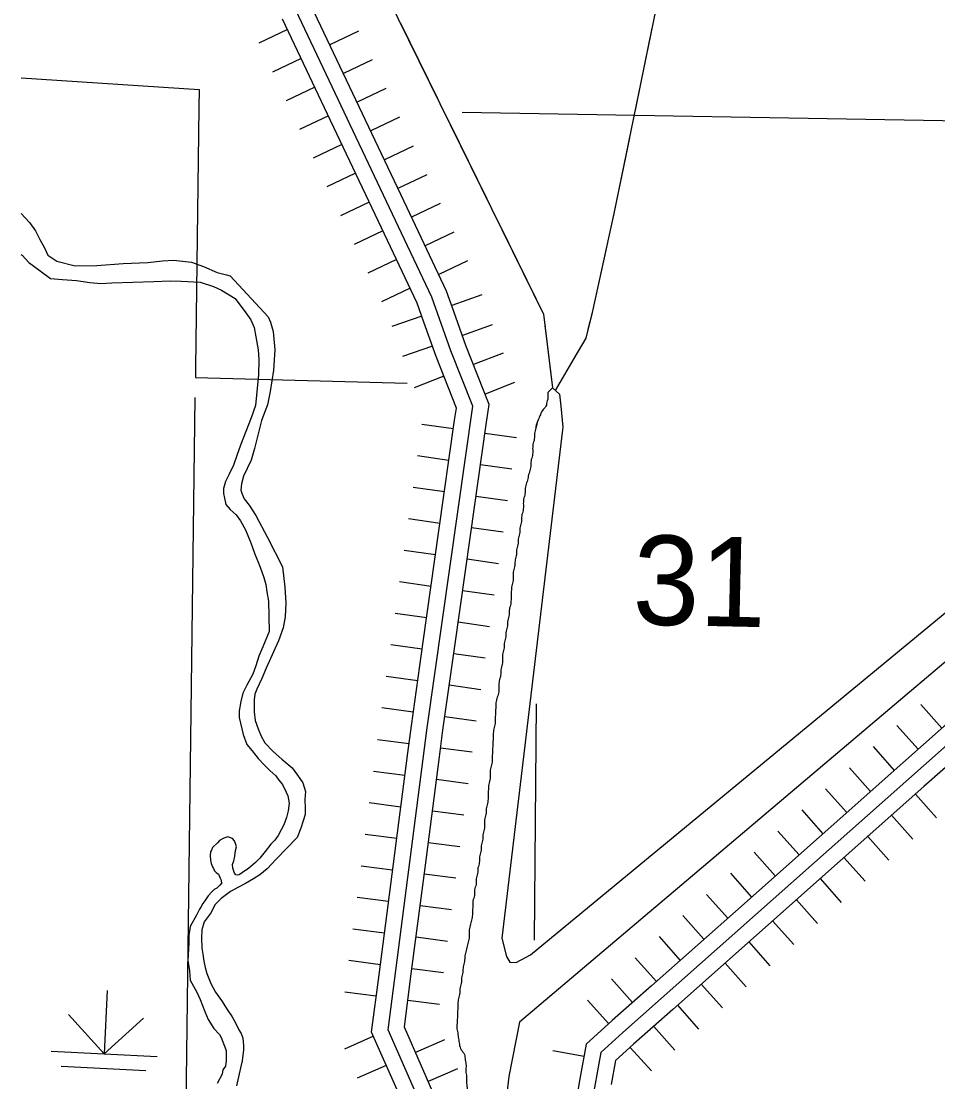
# Model space of a CAD drawing. Extents: x -4306 to 3843, y 131 to 8341.
# Drawn here: x -2796 to -2104, y 5516 to 6317 of the extents above; entities that cross this region are included whole.
import ezdxf

# ---------------------------------------------------------------- set-up
doc = ezdxf.new("R2010")
doc.units = 0
for name, color, linetype in [('32', 7, 'Continuous'), ('4', 7, 'Continuous'), ('52', 7, 'Continuous'), ('54', 7, 'Continuous'), ('55', 7, 'Continuous'), ('56', 7, 'Continuous'), ('59', 7, 'Continuous'), ('63', 7, 'Continuous')]:
    doc.layers.add(name, color=color, linetype=linetype)

msp = doc.modelspace()

# ---------------------------------------------------------------- linework, layer by layer
at = {"layer": '32'}
for p, q in [((-2486.06, 6108.61), (-2632.58, 6417.58)), ((-2486.06, 6108.61), (-2632.58, 6417.58)), ((-2540.91, 6252.29), (-2577.11, 6328.63)), ((-2562.6, 6242.01), (-2598.8, 6318.35)), ((-2504.71, 6175.95), (-2540.91, 6252.29)), ((-2526.4, 6165.67), (-2562.6, 6242.01)), ((-2474.95, 6113.2), (-2504.71, 6175.95)), ((-2497.17, 6104.03), (-2526.4, 6165.67)), ((-2471.68, 6068.01), (-2486.06, 6108.61)), ((-2471.68, 6068.01), (-2486.06, 6108.61)), ((-2469.52, 6097.86), (-2474.95, 6113.2)), ((-2492.15, 6089.85), (-2497.17, 6104.03)), ((-2460.43, 6072.21), (-2469.52, 6097.86)), ((-2482.93, 6063.81), (-2492.15, 6089.85)), ((-2455.31, 6026.29), (-2471.68, 6068.01)), ((-2455.31, 6026.29), (-2471.68, 6068.01)), ((-2442.98, 6027.73), (-2460.43, 6072.21)), ((-2467.63, 6024.84), (-2482.93, 6063.81)), ((-2489.69, 5783.46), (-2455.31, 6026.29)), ((-2489.69, 5783.46), (-2455.31, 6026.29)), ((-2468.91, 6015.84), (-2467.63, 6024.84)), ((-2445.14, 6012.48), (-2442.98, 6027.73)), ((-2480.75, 5932.19), (-2468.91, 6015.84)), ((-2456.98, 5928.82), (-2445.14, 6012.48)), ((-2492.59, 5848.53), (-2480.75, 5932.19)), ((-2468.83, 5845.17), (-2456.98, 5928.82)), ((-2501.58, 5785.07), (-2492.59, 5848.53)), ((-2477.79, 5781.84), (-2468.83, 5845.17)), ((-2011.81, 5846.53), (-2341.92, 5553.64)), ((-2011.81, 5846.53), (-2341.92, 5553.64)), ((-2067.43, 5813.23), (-2130.63, 5757.16)), ((-2051.5, 5795.27), (-2114.7, 5739.2)), ((-2519.23, 5555.73), (-2489.69, 5783.46)), ((-2519.23, 5555.73), (-2489.69, 5783.46)), ((-2504.22, 5764.71), (-2501.58, 5785.07)), ((-2480.42, 5761.62), (-2477.79, 5781.84)), ((-2515.09, 5680.92), (-2504.22, 5764.71)), ((-2491.29, 5677.83), (-2480.42, 5761.62)), ((-2130.63, 5757.16), (-2193.83, 5701.08)), ((-2114.7, 5739.2), (-2177.9, 5683.13)), ((-2193.83, 5701.08), (-2257.03, 5645.01)), ((-2525.96, 5597.13), (-2515.09, 5680.92)), ((-2502.16, 5594.05), (-2491.29, 5677.83)), ((-2177.9, 5683.13), (-2241.09, 5627.05)), ((-2257.03, 5645.01), (-2320.22, 5588.93)), ((-2241.09, 5627.05), (-2304.29, 5570.98)), ((-2531.57, 5553.96), (-2525.96, 5597.13)), ((-2506.9, 5557.51), (-2502.16, 5594.05)), ((-2320.22, 5588.93), (-2349.93, 5562.57)), ((-2304.29, 5570.98), (-2333.91, 5544.71)), ((-2493.45, 5497.18), (-2519.23, 5555.73)), ((-2493.45, 5497.18), (-2519.23, 5555.73)), ((-2490.4, 5520.03), (-2506.9, 5557.51)), ((-2349.93, 5562.57), (-2369.59, 5544.75)), ((-2512.37, 5510.35), (-2531.57, 5553.96)), ((-2341.92, 5553.64), (-2358.5, 5538.6)), ((-2341.92, 5553.64), (-2358.5, 5538.6)), ((-2369.59, 5544.75), (-2374.3, 5518.64)), ((-2333.91, 5544.71), (-2347.42, 5532.45)), ((-2358.5, 5538.6), (-2381.79, 5409.56)), ((-2358.5, 5538.6), (-2381.79, 5409.56)), ((-2347.42, 5532.45), (-2350.68, 5514.38)), ((-2481.02, 5498.73), (-2490.4, 5520.03)), ((-2374.3, 5518.64), (-2389.31, 5435.49))]:
    msp.add_line(p, q, dxfattribs=at)
at = {"layer": '4'}
msp.add_line((-2672.44, 5429.89), (-2664.73, 6032.85), dxfattribs=at)
at = {"layer": '52'}
msp.add_line((-2012.57, 6240.1), (-2463.12, 6248.01), dxfattribs=at)
at = {"layer": '54'}
for p, q in [((-2796.1, 6274.18), (-2661.76, 6265.26)), ((-2661.76, 6265.26), (-2661.94, 6251.5)), ((-2661.94, 6251.5), (-2664.44, 6055.47)), ((-2664.44, 6055.47), (-2664.54, 6047.98)), ((-2664.54, 6047.98), (-2504.64, 6043.66)), ((-2407.42, 5801.55), (-2408.93, 5623.21))]:
    msp.add_line(p, q, dxfattribs=at)
at = {"layer": '55'}
for p, q in [((-2796.1, 6171.68), (-2789.78, 6164.88)), ((-2789.78, 6164.88), (-2785.37, 6158.73)), ((-2785.37, 6158.73), (-2781.93, 6152.26)), ((-2781.93, 6152.26), (-2778.48, 6145.8)), ((-2778.48, 6145.8), (-2775.99, 6140.31)), ((-2775.99, 6140.31), (-2769.32, 6135.73)), ((-2769.32, 6135.73), (-2755.29, 6132.34)), ((-2755.29, 6132.34), (-2738.98, 6132.46)), ((-2738.98, 6132.46), (-2719.13, 6134.13)), ((-2719.13, 6134.13), (-2700.57, 6134.87)), ((-2700.57, 6134.87), (-2689.37, 6136.01)), ((-2689.37, 6136.01), (-2681.04, 6136.55)), ((-2681.04, 6136.55), (-2667.63, 6135.1)), ((-2667.63, 6135.1), (-2658.39, 6131.77)), ((-2658.39, 6131.77), (-2648.21, 6127.15)), ((-2648.21, 6127.15), (-2641.19, 6125.45)), ((-2641.19, 6125.45), (-2638.36, 6124.65))]:
    msp.add_line(p, q, dxfattribs=at)
for points in [[(-2796.1, 6140.83), (-2795.5, 6140.23), (-2790.44, 6134.71), (-2781.88, 6128.5), (-2773.95, 6122.62), (-2765, 6121.86), (-2754.46, 6121.09), (-2744.24, 6119.68), (-2735.93, 6118.93), (-2727.61, 6119.47), (-2695.94, 6120.36), (-2683.78, 6120.85), (-2675.47, 6120.74), (-2661.08, 6119.92), (-2650.89, 6116.58), (-2644.84, 6113.94), (-2634.68, 6107.71), (-2626.48, 6096.69), (-2622.71, 6091.5), (-2620.21, 6085.69), (-2619.01, 6078.61), (-2617.2, 6068.96), (-2616.65, 6061.24), (-2617.1, 6050.01), (-2618.55, 6034.61), (-2619.27, 6026.92), (-2622.58, 6017.64), (-2630.49, 5996.87), (-2633.45, 5989.2), (-2635.77, 5981.84), (-2639.05, 5975.14), (-2641.99, 5969.4), (-2643.33, 5964.28), (-2643.37, 5960.42), (-2642.77, 5956.89), (-2641.55, 5952.05), (-2638.39, 5948.48), (-2633.96, 5944.25), (-2630.49, 5939.71), (-2626.73, 5932.92), (-2622.68, 5923.24), (-2619.89, 5915.5), (-2615.85, 5904.85), (-2613.06, 5897.11), (-2611.52, 5891.63), (-2610.63, 5886.16), (-2609.43, 5879.08), (-2609.04, 5856.27), (-2613.65, 5844.77), (-2616.61, 5837.74), (-2618.93, 5830.39), (-2621.24, 5823.99), (-2625.81, 5815.7), (-2628.76, 5809.64), (-2630.43, 5803.56), (-2631.46, 5796.51), (-2631.52, 5791.37), (-2628.47, 5778.49), (-2625.67, 5771.07), (-2621.89, 5766.2), (-2617.16, 5760.36), (-2612.42, 5755.49), (-2608.31, 5751.26), (-2603.87, 5747.35), (-2601.67, 5744.11)], [(-2638.36, 6124.65), (-2609.62, 6093.7), (-2608.01, 6089.71), (-2605.86, 6082.62), (-2604.73, 6068.8), (-2605.54, 6053.4), (-2608.28, 6037.37), (-2610.31, 6027.45), (-2614.61, 6015.62), (-2619.96, 5994.49), (-2622.62, 5985.53), (-2628.19, 5973.4), (-2629.86, 5967.64), (-2630.23, 5962.83), (-2629.3, 5959.93), (-2627.74, 5956.38), (-2623.96, 5951.51), (-2618.93, 5943.74), (-2610.16, 5927.26), (-2598.9, 5904.96), (-2597.15, 5889.84), (-2596.33, 5877.95), (-2596.77, 5867.36), (-2598.46, 5859.03), (-2601.77, 5849.12), (-2605.7, 5840.82), (-2611.27, 5828.69), (-2614.56, 5820.7), (-2618.17, 5812.72), (-2619.81, 5808.88), (-2620.18, 5804.71), (-2620.28, 5795.72), (-2619.4, 5788.97), (-2617.23, 5782.84), (-2615.05, 5777.35), (-2612.23, 5772.18), (-2605.91, 5765.68), (-2599.26, 5759.82), (-2591.65, 5753.3), (-2587.56, 5747.79), (-2583.47, 5741.96), (-2581.62, 5735.51), (-2582.01, 5729.42), (-2581.76, 5722.99), (-2581.82, 5718.17), (-2583.15, 5713.37), (-2585.13, 5707.94), (-2587.77, 5700.91), (-2603.62, 5684.41), (-2610.42, 5677.11), (-2615.91, 5672.68), (-2620.74, 5669.53), (-2626.86, 5666.08), (-2632.01, 5663.25), (-2638.12, 5660.11), (-2645.21, 5654.74), (-2650.06, 5649.99), (-2652.69, 5644.24), (-2657.88, 5637.24), (-2659.87, 5631.17), (-2659.94, 5625.07), (-2659.71, 5617.36), (-2659.12, 5612.85), (-2658.22, 5607.38)], [(-2601.67, 5744.11), (-2598.83, 5740.87), (-2596.02, 5735.05), (-2594.77, 5732.14), (-2593.87, 5726.67), (-2594.58, 5720.9), (-2595.91, 5715.78), (-2597.89, 5710.35), (-2599.86, 5706.52), (-2602.14, 5702.37), (-2604.74, 5698.87), (-2607.65, 5695.7), (-2611.87, 5690.29), (-2616.09, 5685.21), (-2619.32, 5682.04), (-2622.87, 5678.87), (-2625.46, 5676.65), (-2628.03, 5675.08), (-2629, 5674.45), (-2631.58, 5672.56), (-2633.18, 5672.26), (-2634.14, 5672.59), (-2635.08, 5673.88), (-2635.7, 5675.5), (-2636.32, 5677.75), (-2636.61, 5680.33), (-2635.62, 5683.2), (-2634.94, 5686.73), (-2634.25, 5690.89), (-2633.58, 5693.78), (-2634.2, 5695.39), (-2635.13, 5698.29), (-2636.71, 5699.92), (-2640.21, 5701.24), (-2643.1, 5700.32), (-2646.32, 5698.43), (-2647.94, 5696.85), (-2651.81, 5693.36), (-2652.48, 5691.12), (-2653.13, 5689.85), (-2653.48, 5687.28), (-2653.2, 5683.75), (-2652.59, 5681.17), (-2651.66, 5678.59), (-2651.04, 5677.3), (-2650.09, 5675.68), (-2648.83, 5674.38), (-2647.25, 5673.07), (-2646.3, 5671.46), (-2646, 5670.17), (-2645.06, 5668.55), (-2645.07, 5667.59), (-2644.76, 5666.62), (-2646.06, 5664.71), (-2648.32, 5662.49), (-2650.57, 5661.56), (-2651.87, 5659.97), (-2655.1, 5656.8), (-2657.39, 5652.97), (-2659.01, 5651.06), (-2660.64, 5648.19), (-2661.62, 5646.6), (-2663.9, 5642.13), (-2668.48, 5633.52), (-2669.51, 5626.79), (-2669.57, 5621.65), (-2669.95, 5616.84), (-2670.37, 5607.86), (-2669.17, 5600.13), (-2668.61, 5593.06), (-2663.6, 5584.01), (-2661.1, 5578.52), (-2657.37, 5569.48), (-2654.88, 5563.35), (-2650.8, 5556.55), (-2646.37, 5552), (-2645.12, 5549.74), (-2642.63, 5543.28), (-2641.39, 5540.06), (-2641.44, 5535.56), (-2641.47, 5532.35), (-2641.84, 5528.18), (-2643.79, 5525.32), (-2644.47, 5522.11), (-2648.07, 5515.09)], [(-2658.22, 5607.38), (-2657.31, 5602.55), (-2656.09, 5598.04), (-2652.97, 5590.62), (-2649.53, 5584.15), (-2644.8, 5577.67), (-2640.72, 5570.88), (-2636.95, 5565.37), (-2634.44, 5560.84), (-2631.94, 5555.67), (-2630.05, 5552.76), (-2628.81, 5549.21), (-2628.23, 5543.75), (-2628.27, 5540.54), (-2629.32, 5532.2), (-2630.33, 5528.04), (-2631.67, 5522.28), (-2632.68, 5517.79), (-2633.69, 5513.31)]]:
    msp.add_lwpolyline(points, dxfattribs=at)
at = {"layer": '56'}
for points in [[(-2392.7, 6038.06), (-2378.61, 6062.32), (-2369.74, 6077.64), (-2364.92, 6097.03), (-2348.42, 6171.82), (-2328.07, 6270.89), (-2309.27, 6363.02), (-2286.24, 6472.38), (-2273.45, 6535.73), (-2258.92, 6600.19), (-2235.62, 6710.03), (-2217.15, 6800.47), (-2203.6, 6884.38), (-2197.49, 6944.9), (-2195.73, 7000.54), (-2194.77, 7093.35)], [(-2796.1, 6893.32), (-2660.35, 6614.55), (-2519.4, 6334.93), (-2401.78, 6095.82), (-2394.95, 6040.1)], [(-2509.83, 6315.47), (-2481.86, 6258.61)], [(-2332.44, 6249.65), (-2328.07, 6270.89), (-2319.74, 6311.73)], [(-2472.53, 6239.66), (-2444.56, 6182.8)], [(-2349.5, 6166.9), (-2348.42, 6171.82), (-2336.68, 6228.96)], [(-2435.24, 6163.85), (-2407.27, 6106.99)], [(-2368.04, 6084.48), (-2364.92, 6097.03), (-2354.05, 6146.28)], [(-2400.72, 6087.21), (-2394.95, 6040.1)], [(-2398.45, 6031.65), (-2398.26, 6036.99), (-2394.95, 6040.1), (-2389.74, 6035.36), (-2388.72, 6026.47), (-2387.16, 6010.6), (-2387.62, 6008.6), (-2433.19, 5624.79), (-2429.83, 5610.94), (-2427.32, 5606.74), (-2422.53, 5606.36), (-2411.59, 5612.32), (-2032.72, 5924.64)], [(-2017.93, 5901.63), (-2419.98, 5561.32)], [(-2419.98, 5561.32), (-2428.14, 5520.43), (-2455.18, 5291.97), (-2489.16, 5041.29), (-2521.81, 4920.48), (-2538.06, 4862.99), (-2570.96, 4832.09), (-2659.53, 4768.87)]]:
    msp.add_lwpolyline(points, dxfattribs=at)
for points in [[(-2398.45, 6031.65), (-2399.02, 6030.37), (-2400.06, 6026.24), (-2402.72, 6023.03), (-2404.59, 6018.94), (-2406.46, 6014.86), (-2407.5, 6010.73), (-2406.51, 6014.02), (-2407.54, 6009.9), (-2408.58, 6005.77), (-2408.78, 6001.6), (-2409.82, 5997.48), (-2410.02, 5993.31), (-2410.23, 5989.14), (-2411.27, 5985.01), (-2411.47, 5980.84), (-2412.51, 5976.72), (-2413.54, 5972.59), (-2414.58, 5968.46), (-2415.62, 5964.34), (-2415.82, 5960.17), (-2416.86, 5956.04), (-2417.06, 5951.87), (-2417.27, 5947.71), (-2418.3, 5943.58), (-2418.51, 5939.41), (-2419.55, 5935.28), (-2419.75, 5931.12), (-2420.79, 5926.99), (-2420.99, 5922.82), (-2422.03, 5918.69), (-2422.23, 5914.53), (-2423.27, 5910.4), (-2423.47, 5906.23), (-2424.51, 5902.1), (-2424.71, 5897.94), (-2424.92, 5893.77), (-2425.95, 5889.64), (-2426.16, 5885.47), (-2426.36, 5881.3), (-2426.57, 5877.14), (-2427.6, 5873.01), (-2427.81, 5868.84), (-2428.84, 5864.71), (-2429.05, 5860.55), (-2430.08, 5856.42), (-2430.29, 5852.25), (-2431.33, 5848.13), (-2431.53, 5843.96), (-2432.57, 5839.83), (-2432.77, 5835.66), (-2432.97, 5831.49), (-2434.01, 5827.37), (-2434.22, 5823.2), (-2435.25, 5819.07), (-2435.46, 5814.9), (-2435.66, 5810.74), (-2436.7, 5806.61), (-2437.73, 5802.48), (-2437.94, 5798.31), (-2438.14, 5794.15), (-2438.35, 5789.98), (-2438.55, 5785.81), (-2439.59, 5781.68), (-2439.79, 5777.52), (-2439.99, 5773.35), (-2440.2, 5769.18), (-2440.4, 5765.01), (-2440.61, 5760.84), (-2440.81, 5756.68), (-2441.85, 5752.55), (-2442.05, 5748.38), (-2442.25, 5744.21), (-2443.29, 5740.09), (-2443.5, 5735.92), (-2443.7, 5731.75), (-2443.9, 5727.58), (-2444.94, 5723.46), (-2445.14, 5719.29), (-2446.18, 5715.16), (-2446.39, 5710.99), (-2446.59, 5706.83), (-2447.63, 5702.7), (-2447.83, 5698.53), (-2448.87, 5694.4), (-2449.07, 5690.24), (-2450.11, 5686.11), (-2450.31, 5681.94), (-2451.35, 5677.81)], [(-2451.35, 5677.81), (-2451.55, 5673.65), (-2452.59, 5669.52), (-2452.79, 5665.35), (-2453.83, 5661.22), (-2454.03, 5657.06), (-2455.07, 5652.93), (-2455.28, 5648.76), (-2455.48, 5644.59), (-2455.68, 5640.42), (-2456.72, 5636.3), (-2457.76, 5632.17), (-2457.96, 5628), (-2458.17, 5623.83), (-2459.2, 5619.71), (-2460.24, 5615.58), (-2461.28, 5611.45), (-2461.48, 5607.29), (-2462.52, 5603.16), (-2462.72, 5598.99), (-2463.76, 5594.86), (-2463.96, 5590.7), (-2465, 5586.57), (-2465.2, 5582.4), (-2466.24, 5578.27), (-2466.44, 5574.11), (-2466.65, 5569.94), (-2466.85, 5565.77), (-2467.06, 5561.6), (-2467.26, 5557.43), (-2466.63, 5553.23), (-2466, 5549.02), (-2465.37, 5544.81), (-2463.91, 5540.56), (-2461.57, 5537.1), (-2460.94, 5532.89), (-2460.31, 5528.69), (-2460.52, 5524.52), (-2459.89, 5520.31), (-2460.09, 5516.14), (-2459.46, 5511.93), (-2459.66, 5507.76), (-2459.87, 5503.6), (-2460.07, 5499.43), (-2460.28, 5495.26), (-2461.31, 5491.13), (-2461.52, 5486.97), (-2461.72, 5482.8), (-2461.92, 5478.63), (-2462.13, 5474.46), (-2462.33, 5470.29), (-2462.45, 5467.79), (-2462.66, 5463.63), (-2462.86, 5459.46), (-2463.07, 5455.29), (-2463.27, 5451.12), (-2495.25, 5254.04)]]:
    msp.add_spline(points, degree=3, dxfattribs=at)
at = {"layer": '59'}
for p, q in [((-2731.16, 5585.38), (-2733.5, 5537.43)), ((-2733.5, 5537.43), (-2760.38, 5567.07)), ((-2733.5, 5537.43), (-2703.87, 5564.31)), ((-2773.46, 5539.39), (-2693.55, 5535.48)), ((-2766, 5528.1), (-2702.07, 5524.98))]:
    msp.add_line(p, q, dxfattribs=at)
at = {"layer": '63'}
for p, q in [((-2595.1, 6310.54), (-2616.79, 6300.26)), ((-2595.1, 6310.54), (-2616.79, 6300.26)), ((-2541.44, 6309.42), (-2563.13, 6299.14)), ((-2584.82, 6288.85), (-2606.5, 6278.57)), ((-2531.16, 6287.73), (-2552.84, 6277.45)), ((-2574.53, 6267.16), (-2596.22, 6256.88)), ((-2520.87, 6266.05), (-2542.56, 6255.76)), ((-2520.87, 6266.05), (-2542.56, 6255.76)), ((-2564.25, 6245.48), (-2585.93, 6235.19)), ((-2564.25, 6245.48), (-2585.93, 6235.19)), ((-2510.59, 6244.36), (-2532.27, 6234.07)), ((-2553.96, 6223.79), (-2575.65, 6213.5)), ((-2500.3, 6222.67), (-2521.99, 6212.39)), ((-2543.68, 6202.1), (-2565.36, 6191.82)), ((-2490.02, 6200.98), (-2511.71, 6190.7)), ((-2490.02, 6200.98), (-2511.71, 6190.7)), ((-2533.39, 6180.41), (-2555.08, 6170.13)), ((-2533.39, 6180.41), (-2555.08, 6170.13)), ((-2479.73, 6179.3), (-2501.42, 6169.01)), ((-2523.11, 6158.73), (-2544.8, 6148.44)), ((-2469.45, 6157.61), (-2491.14, 6147.32)), ((-2512.82, 6137.04), (-2534.51, 6126.75)), ((-2459.16, 6135.92), (-2480.85, 6125.64)), ((-2459.16, 6135.92), (-2480.85, 6125.64)), ((-2502.54, 6115.35), (-2524.23, 6105.07)), ((-2502.54, 6115.35), (-2524.23, 6105.07)), ((-2448.5, 6110.4), (-2471.12, 6102.39)), ((-2493.75, 6094.38), (-2516.38, 6086.36)), ((-2440.49, 6087.78), (-2463.11, 6079.76)), ((-2485.74, 6071.75), (-2508.36, 6063.74)), ((-2432.4, 6066.47), (-2454.74, 6057.7)), ((-2432.4, 6066.47), (-2454.74, 6057.7)), ((-2477.09, 6048.93), (-2499.43, 6040.16)), ((-2477.09, 6048.93), (-2499.43, 6040.16)), ((-2423.63, 6044.12), (-2445.97, 6035.36)), ((-2469.85, 6009.19), (-2493.61, 6012.55)), ((-2422.32, 6002.46), (-2446.08, 6005.82)), ((-2473.21, 5985.42), (-2496.98, 5988.79)), ((-2473.21, 5985.42), (-2496.98, 5988.79)), ((-2425.68, 5978.69), (-2449.45, 5982.06)), ((-2425.68, 5978.69), (-2449.45, 5982.06)), ((-2476.58, 5961.66), (-2500.34, 5965.02)), ((-2429.05, 5954.93), (-2452.81, 5958.29)), ((-2479.94, 5937.89), (-2503.71, 5941.26)), ((-2432.41, 5931.16), (-2456.18, 5934.53)), ((-2483.31, 5914.13), (-2507.07, 5917.49)), ((-2483.31, 5914.13), (-2507.07, 5917.49)), ((-2435.78, 5907.4), (-2459.54, 5910.76)), ((-2435.78, 5907.4), (-2459.54, 5910.76)), ((-2486.67, 5890.36), (-2510.44, 5893.72)), ((-2439.14, 5883.63), (-2462.91, 5887)), ((-2490.04, 5866.59), (-2513.8, 5869.96)), ((-2442.51, 5859.87), (-2466.27, 5863.23)), ((-2493.4, 5842.83), (-2517.17, 5846.19)), ((-2493.4, 5842.83), (-2517.17, 5846.19)), ((-2445.87, 5836.1), (-2469.64, 5839.46)), ((-2445.87, 5836.1), (-2469.64, 5839.46)), ((-2496.77, 5819.06), (-2520.53, 5822.43)), ((-2449.23, 5812.33), (-2473, 5815.7)), ((-2500.13, 5795.3), (-2523.9, 5798.66)), ((-2117.11, 5801.24), (-2101.18, 5783.28)), ((-2452.6, 5788.57), (-2476.36, 5791.93)), ((-2135.07, 5785.3), (-2119.14, 5767.35)), ((-2135.07, 5785.3), (-2119.14, 5767.35)), ((-2503.36, 5771.37), (-2527.16, 5774.46)), ((-2503.36, 5771.37), (-2527.16, 5774.46)), ((-2455.75, 5765.2), (-2479.55, 5768.28)), ((-2455.75, 5765.2), (-2479.55, 5768.28)), ((-2153.02, 5769.37), (-2137.09, 5751.42)), ((-2506.44, 5747.57), (-2530.25, 5750.66)), ((-2170.97, 5753.44), (-2155.04, 5735.49)), ((-2458.84, 5741.39), (-2482.64, 5744.48)), ((-2188.93, 5737.51), (-2173, 5719.56)), ((-2188.93, 5737.51), (-2173, 5719.56)), ((-2121.16, 5733.47), (-2105.23, 5715.51)), ((-2509.53, 5723.77), (-2533.34, 5726.85)), ((-2461.93, 5717.59), (-2485.73, 5720.68)), ((-2206.88, 5721.58), (-2190.95, 5703.63)), ((-2139.11, 5717.54), (-2123.18, 5699.58)), ((-2512.62, 5699.96), (-2536.42, 5703.05)), ((-2512.62, 5699.96), (-2536.42, 5703.05)), ((-2224.84, 5705.65), (-2208.91, 5687.7)), ((-2157.07, 5701.61), (-2141.14, 5683.65)), ((-2157.07, 5701.61), (-2141.14, 5683.65)), ((-2465.02, 5693.79), (-2488.82, 5696.87)), ((-2465.02, 5693.79), (-2488.82, 5696.87)), ((-2242.79, 5689.72), (-2226.86, 5671.77)), ((-2242.79, 5689.72), (-2226.86, 5671.77)), ((-2175.02, 5685.68), (-2159.09, 5667.72)), ((-2515.71, 5676.16), (-2539.51, 5679.25)), ((-2468.1, 5669.98), (-2491.91, 5673.07)), ((-2260.75, 5673.79), (-2244.82, 5655.84)), ((-2192.98, 5669.75), (-2177.05, 5651.79)), ((-2518.8, 5652.36), (-2542.6, 5655.45)), ((-2278.7, 5657.86), (-2262.77, 5639.91)), ((-2210.93, 5653.82), (-2195, 5635.86)), ((-2210.93, 5653.82), (-2195, 5635.86)), ((-2471.19, 5646.18), (-2495, 5649.27)), ((-2296.65, 5641.93), (-2280.72, 5623.98)), ((-2296.65, 5641.93), (-2280.72, 5623.98)), ((-2228.89, 5637.89), (-2212.96, 5619.93)), ((-2521.89, 5628.55), (-2545.69, 5631.64)), ((-2521.89, 5628.55), (-2545.69, 5631.64)), ((-2474.28, 5622.38), (-2498.08, 5625.47)), ((-2474.28, 5622.38), (-2498.08, 5625.47)), ((-2314.61, 5626), (-2298.68, 5608.05)), ((-2246.84, 5621.96), (-2230.91, 5604)), ((-2524.98, 5604.75), (-2548.78, 5607.84)), ((-2332.56, 5610.07), (-2316.63, 5592.12)), ((-2264.79, 5606.03), (-2248.86, 5588.07)), ((-2264.79, 5606.03), (-2248.86, 5588.07)), ((-2477.37, 5598.57), (-2501.17, 5601.66)), ((-2350.52, 5594.14), (-2334.59, 5576.19)), ((-2350.52, 5594.14), (-2334.59, 5576.19)), ((-2282.75, 5590.1), (-2266.82, 5572.14)), ((-2528.06, 5580.95), (-2551.87, 5584.04)), ((-2480.46, 5574.77), (-2504.26, 5577.86)), ((-2368.74, 5577.92), (-2352.61, 5560.14)), ((-2300.7, 5574.17), (-2284.77, 5556.21)), ((-2318.66, 5558.24), (-2302.73, 5540.28)), ((-2318.66, 5558.24), (-2302.73, 5540.28)), ((-2530.16, 5550.78), (-2552.13, 5541.1)), ((-2530.16, 5550.78), (-2552.13, 5541.1)), ((-2476.56, 5548.15), (-2498.52, 5538.48)), ((-2394.85, 5539.91), (-2371.23, 5535.65)), ((-2336.49, 5542.36), (-2320.36, 5524.58)), ((-2520.49, 5528.81), (-2542.46, 5519.14)), ((-2466.88, 5526.18), (-2488.85, 5516.51))]:
    msp.add_line(p, q, dxfattribs=at)

# ---------------------------------------------------------------- texts
at = {"layer": '52'}
msp.add_text('31', height=67.591, rotation=358.75468, dxfattribs=at).set_placement((-2334.96, 5861.69))

doc.saveas('drawing.dxf')
